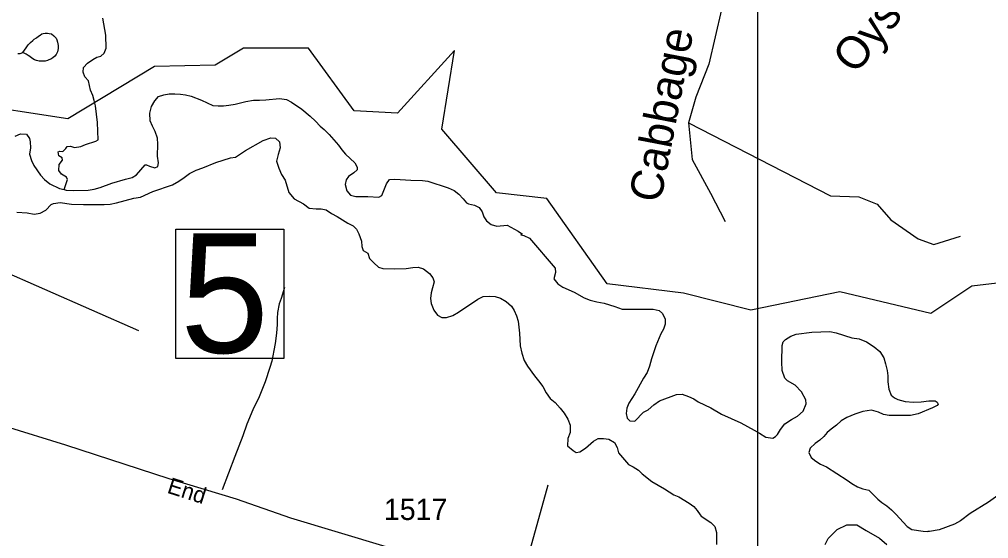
# Model space of a CAD drawing. Extents: x 2290055 to 2389491, y 66597 to 237875.
# Drawn here: x 2343900 to 2346740, y 150018 to 151541 of the extents above; entities that cross this region are included whole.
import ezdxf

# ---------------------------------------------------------------- set-up
doc = ezdxf.new("R2010")
doc.units = 0
for name, color, linetype in [('Exist Boundary Political City Limit New', 7, 'Continuous'), ('Exist Hydrographic Creek Single Shore', 7, 'Continuous'), ('Exist Hydrographic River Shore', 7, 'Continuous'), ('Exist Road Non-System Type 51', 7, 'Continuous'), ('Exist Road Non-System Type 51 Label', 7, 'Continuous'), ('Exist Road Primary US Structure Standard Bridge CELL', 7, 'Continuous'), ('Exist Road Secondary Structure Standard Bridge Number Label', 7, 'Continuous'), ('Exist Road Secondary Type 51 Attributed', 7, 'Continuous'), ('Exist Road Secondary Type 51 Label', 7, 'Continuous'), ('Exist Road Secondary Type 51 Number Label', 7, 'Continuous'), ('Map Preparation Boundary City Limit Buffer Line', 7, 'Continuous'), ('Map Preparation Inset Cut Line', 7, 'Continuous')]:
    doc.layers.add(name, color=color, linetype=linetype)

msp = doc.modelspace()

# ---------------------------------------------------------------- linework, layer by layer
at = {"layer": 'Exist Boundary Political City Limit New'}
msp.add_lwpolyline([(2349898.5, 155096.5), (2347115.8, 150577.3), (2346798.2, 150771.2), (2346691.2, 150757.8), (2346571, 150677.6), (2346303.8, 150741.1), (2346043.2, 150687.6), (2345846, 150737.8), (2345622.2, 150764.5), (2345445.2, 151015.2), (2345298.2, 151031.9), (2345137.8, 151219.1), (2345174.5, 151449.7), (2345007.5, 151265.9), (2344880.5, 151272.6), (2344747, 151456.4), (2344556.5, 151456.4), (2344473, 151406.3), (2344296, 151402.9), (2344042, 151249.2), (2343734.8, 151296)], dxfattribs=at)
at = {"layer": 'Exist Hydrographic Creek Single Shore'}
msp.add_lwpolyline([(2344030.8, 151041.2), (2344040.7, 151070.9), (2344037.7, 151078), (2344023.2, 151086.6), (2344015.7, 151097.7), (2344016.7, 151115.3), (2344026.5, 151127.5), (2344025.2, 151134.6), (2344015.7, 151140.9), (2344013, 151152.2), (2344018.2, 151154.3), (2344027, 151153.6), (2344036.2, 151161.6), (2344039.5, 151167.8), (2344049.5, 151168.4), (2344061.2, 151165), (2344079.5, 151167.5), (2344093.7, 151173.9), (2344124.2, 151183.2), (2344130.7, 151187), (2344128.7, 151238.2), (2344122.5, 151286.6), (2344119.2, 151303.1), (2344114.7, 151317.7), (2344108.5, 151333.4), (2344102.5, 151360.5), (2344091.7, 151372.4), (2344086.5, 151386.1), (2344088, 151399.3), (2344099.7, 151412.2), (2344114.7, 151423), (2344126.7, 151430.2), (2344138.2, 151433), (2344148.5, 151441.3), (2344153.7, 151456.5), (2344153, 151494.3), (2344144.7, 151544.3)], dxfattribs=at)
at = {"layer": 'Exist Hydrographic River Shore'}
for points in [[(2344230.5, 151076.6), (2344243.2, 151084.6), (2344268.5, 151113.6), (2344272.5, 151114.4), (2344281, 151110.4), (2344296.5, 151105), (2344305.5, 151108.8), (2344307.5, 151120.1), (2344304.2, 151139.2), (2344305.7, 151174.7), (2344304, 151192.2), (2344297.5, 151212.1), (2344289.7, 151227.6), (2344283.2, 151243.2), (2344282, 151265.7), (2344287, 151285.1), (2344296.5, 151301.4), (2344307.5, 151314), (2344323, 151319.6), (2344339, 151322.5), (2344355.5, 151322.4), (2344371.5, 151321.7), (2344387, 151319.2), (2344403, 151315.4), (2344433, 151303.9), (2344467, 151287.7), (2344482.2, 151286.7), (2344497.7, 151287.1), (2344514, 151288.8), (2344532.5, 151292), (2344563.2, 151300), (2344586, 151303.6), (2344603.2, 151303.6), (2344621.5, 151304.7), (2344662.5, 151309), (2344682.2, 151305.9), (2344697.5, 151297.9), (2344727, 151277.6), (2344751.5, 151257.2), (2344767.5, 151242.2), (2344781.2, 151227.6), (2344792.7, 151217.7), (2344807.2, 151202.6), (2344834.7, 151171.6), (2344845, 151157.7), (2344855.7, 151144.9), (2344882.7, 151120.3), (2344890, 151107.1), (2344889.2, 151099.3), (2344880.2, 151090.3), (2344864.5, 151080), (2344857, 151070.4), (2344854.5, 151056.1), (2344859, 151037.6), (2344870, 151025.3), (2344886.2, 151021.3), (2344920.5, 151020.8)], [(2343887.5, 151198.3), (2343903.2, 151205.2), (2343920.7, 151204.3), (2343929.7, 151191.7), (2343931.7, 151181.5), (2343932, 151164.2), (2343929.2, 151145.7), (2343935.2, 151126.7), (2343942.2, 151111.8), (2343961.7, 151083.9), (2343973.7, 151070.6), (2343988.7, 151058.7), (2344017.7, 151044.4), (2344030.8, 151041.2)], [(2343892.2, 150975.4), (2343922.7, 150973.7), (2343942.7, 150969), (2343961, 150972), (2343977.5, 150981.5), (2343992.5, 150997.7), (2344000, 151000.7), (2344019.2, 151003.2), (2344052, 150998.9), (2344088, 150998.1), (2344148.2, 150997.8), (2344165.5, 150998.8), (2344184.7, 151003), (2344235.5, 151016.7), (2344254.5, 151019.3), (2344290.7, 151035.4), (2344348, 151055.6), (2344366.5, 151065.8), (2344382.2, 151076.4), (2344398, 151088.4), (2344417.7, 151098), (2344437.2, 151105.1), (2344475.2, 151121), (2344518, 151134.3), (2344533.5, 151136.1), (2344562.7, 151155.9), (2344614.2, 151185.8), (2344637, 151193.4), (2344650, 151192.6), (2344662, 151181.1), (2344664.2, 151164.2), (2344658.5, 151144.8), (2344653.7, 151124.6), (2344659.7, 151103.8), (2344668.2, 151085.9), (2344678.2, 151068.8), (2344689.7, 151032.5), (2344705.2, 151014.1), (2344732, 151000.1), (2344749.2, 150987), (2344769, 150984.8), (2344784, 150984.7), (2344799.2, 150982), (2344814.7, 150971.7), (2344831, 150962.8), (2344862.2, 150943), (2344877.5, 150935), (2344887.5, 150925.2), (2344895, 150911.8), (2344902.5, 150889.9), (2344903, 150874.4), (2344907.5, 150863), (2344921.2, 150855.3), (2344926.2, 150838.8)], [(2344030.8, 151041.2), (2344036.5, 151039.8), (2344059.5, 151039.1), (2344101, 151039.8), (2344119, 151042.3), (2344136.2, 151047.3), (2344170.7, 151060.1), (2344210.5, 151071.7), (2344230.5, 151076.6)], [(2344920.5, 151020.8), (2344953.5, 151018.9), (2344962, 151024), (2344975.5, 151058.5), (2344984.5, 151070.6), (2345000, 151071.8), (2345046.7, 151069.1), (2345081.5, 151068), (2345097.2, 151066.2), (2345156.2, 151047), (2345173.7, 151038.3), (2345187.7, 151027.7), (2345200.5, 151014.4), (2345210, 151002.4), (2345216, 150999.5), (2345233.2, 150995.6), (2345247.5, 150988.6), (2345256, 150976.4), (2345260.5, 150961.9), (2345268.7, 150949.4), (2345282, 150938.9), (2345299, 150934.3), (2345329.2, 150936.8), (2345361.5, 150919.3), (2345374.5, 150910.2), (2345372.5, 150910.8), (2345369, 150909), (2345378.5, 150907), (2345395.2, 150899.1), (2345469.7, 150810.7), (2345470.5, 150797.9), (2345466.2, 150779.5), (2345478, 150764.8), (2345492, 150755.3), (2345525.5, 150740.2), (2345554.5, 150723.4), (2345572.5, 150717.2), (2345592.5, 150711.9), (2345613.2, 150707.9), (2345629.5, 150703.4), (2345645.2, 150698.7), (2345666.5, 150690.5), (2345757, 150690.8), (2345774.7, 150687.2), (2345785, 150678), (2345792.5, 150661.7), (2345792.2, 150647.1), (2345787.2, 150632.1), (2345779.2, 150617.8), (2345764.5, 150583.2), (2345752, 150545.3), (2345746.5, 150523.9), (2345740, 150505.3), (2345728.5, 150488.4), (2345703.2, 150442.2), (2345685.5, 150414.6), (2345680, 150400.1), (2345677.7, 150385), (2345680.7, 150370.9), (2345689, 150362.7), (2345703.7, 150362.6), (2345728.5, 150388.4), (2345742.7, 150395.4), (2345759.5, 150409.6), (2345775.7, 150421.9), (2345825.2, 150440.1), (2345841.7, 150441.8), (2345861.2, 150434.6), (2345876, 150427.6), (2345889.5, 150419.2), (2345925.7, 150400.8), (2345957.5, 150382.7), (2346014.5, 150357.7), (2346052.7, 150335.6), (2346069, 150327.3), (2346087.5, 150315.6), (2346108, 150312.7), (2346115.5, 150316.7), (2346122, 150323.4), (2346130.7, 150337.6), (2346143, 150354.3), (2346162.5, 150366.8), (2346180.2, 150376.3), (2346196.5, 150391.2), (2346205.5, 150412.9), (2346205, 150424.3), (2346191.7, 150448.3), (2346173, 150467.6), (2346150.7, 150480.8), (2346143.5, 150488.6), (2346135.7, 150510.8), (2346134.2, 150535.9), (2346135.5, 150584.3), (2346138.5, 150594.5), (2346144.7, 150601.9), (2346161, 150611.8), (2346176.2, 150617.1), (2346222.2, 150623.5), (2346274.7, 150624.9), (2346293.5, 150620.9)], [(2344926.2, 150838.8), (2344938, 150826.2), (2344952, 150814), (2344965.2, 150809.9), (2345000, 150809.3), (2345033.2, 150809.9), (2345052.7, 150812.7), (2345068.2, 150813.4), (2345084, 150808.7), (2345101.5, 150795.2), (2345111.5, 150782.8), (2345115.5, 150770.4), (2345110.2, 150752.9), (2345107, 150738.2), (2345104.7, 150722.3), (2345106.7, 150706.9), (2345114.5, 150687.3), (2345125, 150673.1), (2345137.5, 150666.4), (2345151.2, 150666.3), (2345170, 150671.7), (2345186.7, 150682.1), (2345243.2, 150720.4), (2345259, 150727.4), (2345278.5, 150728.4), (2345294.2, 150728.2), (2345309.5, 150722.8), (2345326, 150712.7), (2345341.5, 150699.5), (2345350, 150686.9), (2345356.7, 150670.8), (2345361.5, 150655.5), (2345365.2, 150619.9), (2345367.7, 150583.3), (2345372.5, 150562), (2345379.5, 150539.6), (2345389.2, 150523.5), (2345409, 150494.8), (2345421.5, 150480.9), (2345434.2, 150463.5), (2345443.5, 150444.9), (2345455.7, 150428.5), (2345470, 150417.1), (2345485, 150400.3), (2345496, 150385.7), (2345507.2, 150367.7), (2345513.5, 150350.6), (2345513.5, 150328.4), (2345506.7, 150310.9), (2345506, 150290.1), (2345522.5, 150275.9), (2345531.7, 150270.1), (2345542.7, 150271.9), (2345559, 150282.9), (2345582.7, 150303.8), (2345596.2, 150310.9), (2345611.7, 150311.4), (2345627.7, 150309.1), (2345643.5, 150300), (2345651.5, 150285), (2345655.2, 150268.9), (2345684.7, 150234.8), (2345698.2, 150228), (2345714, 150218), (2345724.7, 150207.5), (2345753.7, 150184.9), (2345790.7, 150163.6), (2345818.2, 150146.2), (2345832.7, 150139.9), (2345862.5, 150121.6), (2345876.2, 150111.8), (2345886.2, 150100.4), (2345894.5, 150086.9), (2345898.2, 150083.1), (2345926.5, 150064.9), (2345938, 150053.1), (2345942.5, 150036), (2345942.7, 150000)], [(2346293.5, 150620.9), (2346339.5, 150606.7), (2346360.5, 150603.8), (2346382.2, 150594.9), (2346405.2, 150579.7), (2346421.5, 150566.5), (2346433, 150547.5), (2346438.5, 150529.8), (2346443, 150510.3), (2346444.5, 150495.3), (2346444.5, 150477.9), (2346448, 150455.7), (2346454.7, 150438.1), (2346464.2, 150430.2), (2346474.5, 150425.6), (2346495.7, 150420.2), (2346520, 150418.3), (2346543, 150418.7), (2346565, 150421.4), (2346583.2, 150421.9), (2346589.7, 150417.4), (2346592.5, 150411.7), (2346589.2, 150407.9), (2346576, 150400.9), (2346534.2, 150383.5), (2346511, 150378.8), (2346449, 150378.7), (2346432.5, 150381.2), (2346417.7, 150388.9), (2346397.5, 150393.9), (2346371.5, 150390.6), (2346348, 150382.9), (2346324.5, 150373), (2346308, 150363), (2346294, 150350.4), (2346279, 150338.9), (2346267, 150328.8), (2346257, 150317.4), (2346245.5, 150306.8), (2346232.2, 150296.3), (2346217.5, 150282.5), (2346213.5, 150270.1), (2346220.7, 150255.7), (2346234, 150244.9), (2346248, 150236.1), (2346264.7, 150228.4), (2346326, 150189.1), (2346339.2, 150178.8), (2346356.5, 150169.7), (2346372, 150164.1), (2346389, 150159.6), (2346415.2, 150133.6), (2346427.5, 150123.4), (2346442, 150113.9), (2346455.7, 150101.8), (2346468.5, 150089.6), (2346501.5, 150053.3), (2346515, 150044), (2346548.5, 150039.1), (2346561.7, 150038.4)], [(2346784.7, 150156.6), (2346740, 150124.2), (2346686.5, 150091.1), (2346657.5, 150070), (2346640.5, 150060), (2346595.2, 150043.6), (2346567.5, 150038.1), (2346561.7, 150038.4)], [(2346261, 150000), (2346270.5, 150017.9), (2346296.2, 150044.7), (2346325, 150058.5), (2346353.8, 150057.6), (2346381.6, 150041.7), (2346420.3, 150018.9), (2346442, 150000)]]:
    msp.add_lwpolyline(points, dxfattribs=at)
at = {"layer": 'Exist Road Non-System Type 51'}
msp.add_line((2345448.1, 150174.4), (2345367.7, 149881.7), dxfattribs=at)
for points in [[(2345957.7, 151570.1), (2345919.9, 151409.1), (2345882.4, 151312.5), (2345860.9, 151237.4), (2345871.6, 151130), (2345925.3, 151030.7), (2345968.2, 150947.5)], [(2343909.7, 151443.8), (2343919.7, 151457.6), (2343925.6, 151465.7), (2343929.1, 151469.8), (2343931.9, 151473.2), (2343938.9, 151479), (2343943.3, 151482.5), (2343949.4, 151487), (2343955.4, 151491.8), (2343960.6, 151494.7), (2343965.4, 151497.8), (2343969.6, 151499), (2343975.5, 151499.9), (2343981.7, 151500.1), (2343987.3, 151499.7), (2343993.6, 151497.9), (2344001, 151492.7), (2344007.5, 151485.4), (2344009.7, 151480.2), (2344011.6, 151474), (2344013, 151463.9), (2344013, 151455.7), (2344011.1, 151445.5), (2344009.6, 151441.5), (2344007.8, 151438.1), (2344003.7, 151432.7), (2343998, 151428.2), (2343991.9, 151424), (2343986.4, 151421.8), (2343981.9, 151420), (2343974.8, 151418.1), (2343967.9, 151417.8), (2343958, 151418.1), (2343950.1, 151419.8), (2343943.8, 151421.8), (2343936.3, 151427.1), (2343929.9, 151431.8), (2343925.5, 151434.9), (2343919.5, 151438.6), (2343909.7, 151443.8)], [(2343895.4, 151440.2), (2343902, 151440.8), (2343909.7, 151443.8)], [(2345860.9, 151237.4), (2346276.7, 151022.6), (2346359.8, 151019.9), (2346413.5, 150998.5), (2346453.7, 150952.8), (2346534.2, 150896.5), (2346579.8, 150880.4), (2346657.6, 150904.5)], [(2344676.5, 150754), (2344666.6, 150721.8), (2344660.7, 150705.8), (2344655.7, 150681), (2344654.8, 150663.5), (2344655.2, 150645.5), (2344653.2, 150619.8), (2344649.1, 150590.4), (2344645.4, 150569.6), (2344639.4, 150538.5), (2344633.9, 150519.6), (2344620.1, 150477.4), (2344602.2, 150433.3), (2344584.3, 150395.2), (2344566.6, 150353.2), (2344554.9, 150318.9), (2344531.3, 150258.9), (2344493.8, 150160.6)]]:
    msp.add_lwpolyline(points, dxfattribs=at)
at = {"layer": 'Exist Road Primary US Structure Standard Bridge CELL'}
msp.add_line((2343152.7, 151109.8), (2344249.2, 150628.4), dxfattribs=at)
at = {"layer": 'Exist Road Secondary Structure Standard Bridge Number Label'}
msp.add_lwpolyline([(2344358.2, 150925.1), (2344675.2, 150925.1), (2344675.2, 150545.7), (2344358.2, 150545.7)], close=True, dxfattribs=at)
at = {"layer": 'Exist Road Secondary Type 51 Attributed'}
msp.add_lwpolyline([(2342975.9, 150628.9), (2343130.5, 150573.7), (2343313.2, 150513.1), (2343582.7, 150429.9), (2343784.5, 150367.7), (2343858.1, 150347.6), (2344034.4, 150292.4), (2344337.4, 150194.2), (2344534.7, 150134.1), (2344694.3, 150078.9), (2344973.5, 149994.5), (2345201.2, 149923), (2345375.9, 149867.9)], dxfattribs=at)
at = {"layer": 'Map Preparation Boundary City Limit Buffer Line'}
msp.add_lwpolyline([(2349898.5, 155096.5), (2347115.8, 150577.3), (2346798.2, 150771.2), (2346691.2, 150757.8), (2346571, 150677.6), (2346303.8, 150741.1), (2346043.2, 150687.6), (2345846, 150737.8), (2345622.2, 150764.5), (2345445.2, 151015.2), (2345298.2, 151031.9), (2345137.8, 151219.1), (2345174.5, 151449.7), (2345007.5, 151265.9), (2344880.5, 151272.6), (2344747, 151456.4), (2344556.5, 151456.4), (2344473, 151406.3), (2344296, 151402.9), (2344042, 151249.2), (2343734.8, 151296)], dxfattribs=at)
at = {"layer": 'Map Preparation Inset Cut Line'}
msp.add_lwpolyline([(2325416.4, 141886.2), (2343900.4, 141886.2), (2346064.1, 148689.8), (2346393.7, 149726.2), (2346064.1, 149726.2), (2346064.1, 156758), (2331912.3, 156758), (2331912.3, 149726.2), (2325417.5, 149726.2)], close=True, dxfattribs=at)

# ---------------------------------------------------------------- texts
at = {"layer": 'Exist Road Non-System Type 51 Label'}
for s, rotation, p in [('Oyster Bay', 50.9379, (2346349.4, 151376.4)), ('Cabbage', 79.1138, (2345778.6, 150999.6))]:
    msp.add_text(s, height=95, rotation=rotation, dxfattribs=at).set_placement(p)
at = {"layer": 'Exist Road Secondary Structure Standard Bridge Number Label'}
msp.add_text('5', height=350, dxfattribs=at).set_placement((2344370.8, 150562.6))
at = {"layer": 'Exist Road Secondary Type 51 Label'}
msp.add_text('End', height=47.5, rotation=342.446, dxfattribs=at).set_placement((2344330.1, 150152.5))
at = {"layer": 'Exist Road Secondary Type 51 Number Label'}
msp.add_text('1517', height=62.5, dxfattribs=at).set_placement((2344968, 150072.2))

doc.saveas('drawing.dxf')
